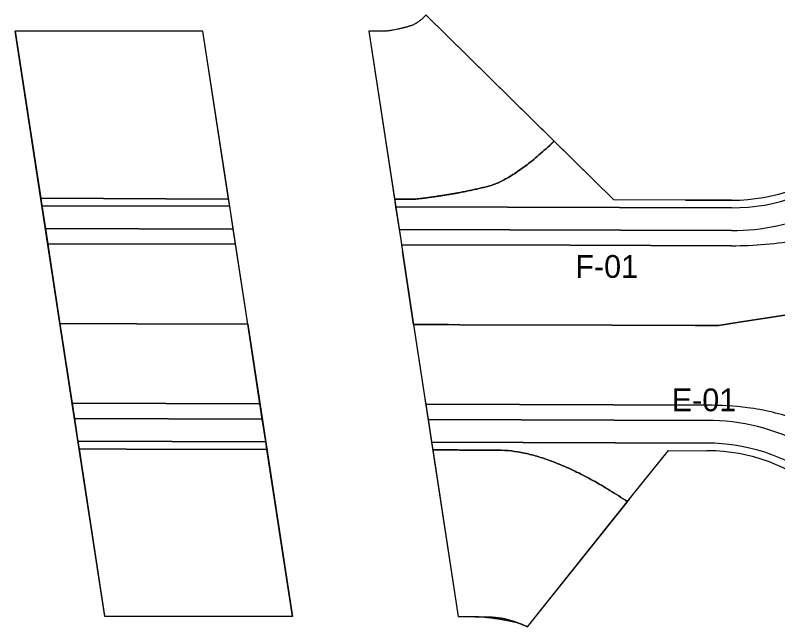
# Model space of a CAD drawing. Extents: x 5196716 to 5200291, y 3709146 to 3713154.
# Drawn here: x 5197139.9 to 5197340.6, y 3709270.7 to 3709431.8 of the extents above; entities that cross this region are included whole.
import ezdxf

# ---------------------------------------------------------------- set-up
doc = ezdxf.new("R2010")
doc.units = 0
for name, color, linetype in [('Drainage-Area', 7, 'Continuous'), ('dsnTextNote', 7, 'Continuous'), ('Level 1', 7, 'Continuous'), ('Level 2', 7, 'Continuous'), ('Level 3', 7, 'Continuous'), ('Level 4', 7, 'Continuous')]:
    doc.layers.add(name, color=color, linetype=linetype)

msp = doc.modelspace()

# ---------------------------------------------------------------- linework, layer by layer
at = {"layer": 'Drainage-Area'}
for p, q in [((5197151.63, 3709350.57), (5197139.87, 3709427.59)), ((5197189.27, 3709427.57), (5197139.87, 3709427.59)), ((5197139.87, 3709427.59), (5197148.88, 3709368.54)), ((5197201.05, 3709350.42), (5197195.7, 3709385.44)), ((5197195.7, 3709385.44), (5197195.7, 3709385.44)), ((5197195.7, 3709385.44), (5197195.7, 3709385.44)), ((5197316.34, 3709383.09), (5197328.45, 3709383.06)), ((5197148.88, 3709368.54), (5197151.63, 3709350.57)), ((5197151.63, 3709350.57), (5197201.05, 3709350.42))]:
    msp.add_line(p, q, dxfattribs=at)
for points in [[(5197195.7, 3709385.44), (5197189.27, 3709427.57)], [(5197251.88, 3709350.28), (5197244.74, 3709350.3), (5197241.79, 3709369.59)], [(5197318.88, 3709350.08), (5197325, 3709350.07), (5197330.45, 3709350.92)]]:
    msp.add_lwpolyline(points, dxfattribs=at)
msp.add_lwpolyline([(5197151.63, 3709350.57), (5197201.05, 3709350.42), (5197212.81, 3709273.4), (5197163.41, 3709273.42)], close=True, dxfattribs=at)
at = {"layer": 'Level 1'}
for p, q in [((5197297.45, 3709383.15), (5197248, 3709431.77)), ((5197235.97, 3709427.56), (5197232.94, 3709427.56)), ((5197232.94, 3709427.56), (5197241.42, 3709372.05)), ((5197322.58, 3709383.07), (5197297.45, 3709383.15)), ((5197328.45, 3709383.06), (5197322.58, 3709383.07)), ((5197241.42, 3709372.05), (5197241.53, 3709371.31)), ((5197241.53, 3709371.31), (5197241.79, 3709369.59)), ((5197346.68, 3709353.45), (5197325, 3709350.07)), ((5197330.45, 3709350.92), (5197346.68, 3709353.45)), ((5197256.88, 3709350.26), (5197244.74, 3709350.3)), ((5197244.74, 3709350.3), (5197247.46, 3709332.48)), ((5197251.88, 3709350.28), (5197253.88, 3709350.27)), ((5197296.88, 3709350.15), (5197256.88, 3709350.26)), ((5197324.26, 3709350.07), (5197296.88, 3709350.15)), ((5197325, 3709350.07), (5197324.26, 3709350.07)), ((5197247.46, 3709332.48), (5197247.95, 3709329.29)), ((5197247.95, 3709329.29), (5197248.55, 3709325.3)), ((5197302.39, 3709305.33), (5197311.79, 3709317.1)), ((5197311.79, 3709317.1), (5197321.94, 3709317.07)), ((5197274.72, 3709270.7), (5197302.39, 3709305.33)), ((5197256.48, 3709273.38), (5197259.52, 3709273.38))]:
    msp.add_line(p, q, dxfattribs=at)
for points in [[(5197241.79, 3709369.59), (5197244.74, 3709350.3), (5197251.88, 3709350.28)], [(5197324.26, 3709350.07), (5197325, 3709350.07), (5197330.45, 3709350.92)], [(5197253.88, 3709350.27), (5197256.88, 3709350.26), (5197296.88, 3709350.15)], [(5197296.88, 3709350.15), (5197318.88, 3709350.08), (5197324.26, 3709350.07)], [(5197248.55, 3709325.3), (5197254.02, 3709289.52), (5197256.48, 3709273.38)], [(5197259.52, 3709273.38), (5197259.59, 3709273.38)]]:
    msp.add_lwpolyline(points, dxfattribs=at)
for centre, start, end in [((5197328.59, 3709431.06), 269.8345, 309.8603), ((5197321.8, 3709269.07), 89.4347, 89.8345), ((5197321.8, 3709269.07), 50.7893, 89.4347)]:
    msp.add_arc(centre, 48, start, end, dxfattribs=at)
for points in [[(5197247.8, 3709431.58), (5197245.73, 3709429.59), (5197242.85, 3709428.58), (5197240.45, 3709428.08)], [(5197248, 3709431.77), (5197247.93, 3709431.7), (5197247.87, 3709431.64), (5197247.8, 3709431.58)], [(5197240.45, 3709428.08), (5197237.95, 3709427.55), (5197235.97, 3709427.56), (5197235.97, 3709427.56)], [(5197259.59, 3709273.38), (5197260.46, 3709273.37), (5197269.42, 3709273.2), (5197274.72, 3709270.7)]]:
    msp.add_open_spline(points, degree=2, dxfattribs=at)
at = {"layer": 'Level 2'}
for p, q in [((5197196.31, 3709381.44), (5197146.89, 3709381.58)), ((5197146.89, 3709381.58), (5197147.81, 3709375.58)), ((5197197.23, 3709375.43), (5197196.31, 3709381.44)), ((5197328.45, 3709381.06), (5197240, 3709381.31)), ((5197240, 3709381.31), (5197240.92, 3709375.31)), ((5197147.81, 3709375.58), (5197197.23, 3709375.43)), ((5197240.92, 3709375.31), (5197328.43, 3709375.06)), ((5197148.42, 3709371.58), (5197148.88, 3709368.54)), ((5197197.84, 3709371.43), (5197148.42, 3709371.58)), ((5197201.05, 3709350.42), (5197197.84, 3709371.43)), ((5197241.53, 3709371.31), (5197241.79, 3709369.59)), ((5197148.88, 3709368.54), (5197151.63, 3709350.57)), ((5197330.45, 3709350.92), (5197346.68, 3709353.45)), ((5197346.68, 3709353.45), (5197330.45, 3709350.92)), ((5197325, 3709350.07), (5197330.45, 3709350.92)), ((5197330.45, 3709350.92), (5197325, 3709350.07)), ((5197151.63, 3709350.57), (5197171.88, 3709350.51)), ((5197171.88, 3709350.51), (5197201.05, 3709350.42)), ((5197201.05, 3709350.42), (5197171.88, 3709350.51)), ((5197204.26, 3709329.41), (5197201.05, 3709350.42)), ((5197251.88, 3709350.28), (5197244.74, 3709350.3)), ((5197244.74, 3709350.3), (5197247.46, 3709332.48)), ((5197251.88, 3709350.28), (5197253.88, 3709350.27)), ((5197253.88, 3709350.27), (5197251.88, 3709350.28)), ((5197253.88, 3709350.27), (5197256.88, 3709350.26)), ((5197256.88, 3709350.26), (5197296.88, 3709350.15)), ((5197318.88, 3709350.08), (5197296.88, 3709350.15)), ((5197324.26, 3709350.07), (5197325, 3709350.07)), ((5197247.46, 3709332.48), (5197247.95, 3709329.29)), ((5197154.84, 3709329.56), (5197154.84, 3709329.56)), ((5197154.84, 3709329.56), (5197204.26, 3709329.41)), ((5197247.95, 3709329.29), (5197321.98, 3709329.07)), ((5197155.45, 3709325.56), (5197156.36, 3709319.55)), ((5197204.87, 3709325.41), (5197155.45, 3709325.56)), ((5197205.79, 3709319.41), (5197204.87, 3709325.41)), ((5197321.97, 3709325.07), (5197248.55, 3709325.3)), ((5197248.55, 3709325.3), (5197249.47, 3709319.28)), ((5197156.36, 3709319.55), (5197205.79, 3709319.41)), ((5197249.47, 3709319.28), (5197321.95, 3709319.07))]:
    msp.add_line(p, q, dxfattribs=at)
for points in [[(5197328.42, 3709371.06), (5197285.89, 3709371.18), (5197241.53, 3709371.31)], [(5197241.79, 3709369.59), (5197244.74, 3709350.3), (5197251.88, 3709350.28)], [(5197171.88, 3709350.51), (5197151.63, 3709350.57), (5197154.84, 3709329.56)], [(5197296.88, 3709350.15), (5197256.88, 3709350.26), (5197253.88, 3709350.27)], [(5197296.88, 3709350.15), (5197318.88, 3709350.08), (5197324.26, 3709350.07)], [(5197325, 3709350.07), (5197324.26, 3709350.07), (5197318.88, 3709350.08)]]:
    msp.add_lwpolyline(points, dxfattribs=at)
for centre, radius, start, end in [((5197328.59, 3709431.06), 50, 269.8345, 309.4106), ((5197328.59, 3709431.06), 56, 269.8345, 294.4582), ((5197328.7, 3709468.56), 97.5, 269.8354, 280.3656), ((5197321.72, 3709241.57), 87.5, 82.8549, 89.8345), ((5197325.15, 3709268.86), 60, 70.1272, 82.8549), ((5197321.8, 3709269.07), 56, 62.2868, 89.8345), ((5197321.8, 3709269.07), 50, 54.334, 89.8345)]:
    msp.add_arc(centre, radius, start, end, dxfattribs=at)
at = {"layer": 'Level 3'}
for p, q in [((5197281.71, 3709398.62), (5197248, 3709431.77)), ((5197139.87, 3709427.59), (5197146.59, 3709383.58)), ((5197189.27, 3709427.57), (5197139.87, 3709427.59)), ((5197196.02, 3709383.36), (5197189.27, 3709427.57)), ((5197235.97, 3709427.56), (5197232.94, 3709427.56)), ((5197232.94, 3709427.56), (5197239.7, 3709383.31)), ((5197146.59, 3709383.58), (5197196.02, 3709383.36)), ((5197239.7, 3709383.31), (5197242.73, 3709383.3)), ((5197169.15, 3709317.52), (5197156.67, 3709317.55)), ((5197156.67, 3709317.55), (5197163.39, 3709273.54)), ((5197206.09, 3709317.41), (5197169.15, 3709317.52)), ((5197212.81, 3709273.4), (5197206.09, 3709317.41)), ((5197252.81, 3709317.27), (5197249.78, 3709317.28)), ((5197249.78, 3709317.28), (5197254.02, 3709289.52)), ((5197274.72, 3709270.7), (5197301.05, 3709303.65)), ((5197254.02, 3709289.52), (5197256.48, 3709273.4)), ((5197163.39, 3709273.54), (5197212.81, 3709273.4)), ((5197256.48, 3709273.4), (5197256.48, 3709273.38)), ((5197256.48, 3709273.38), (5197259.52, 3709273.38))]:
    msp.add_line(p, q, dxfattribs=at)
for points in [[(5197247.8, 3709431.58), (5197245.73, 3709429.59), (5197242.85, 3709428.58), (5197240.45, 3709428.08)], [(5197248, 3709431.77), (5197247.93, 3709431.7), (5197247.87, 3709431.64), (5197247.8, 3709431.58)], [(5197240.45, 3709428.08), (5197237.95, 3709427.55), (5197235.97, 3709427.56), (5197235.97, 3709427.56)], [(5197249.78, 3709383.91), (5197257.64, 3709385.03), (5197270.57, 3709388.26), (5197280.55, 3709397.5)], [(5197280.55, 3709397.5), (5197280.94, 3709397.87), (5197281.33, 3709398.24), (5197281.71, 3709398.62)], [(5197242.73, 3709383.3), (5197242.73, 3709383.3), (5197245.51, 3709383.3), (5197249.78, 3709383.91)], [(5197301.05, 3709303.65), (5197280.77, 3709317.19), (5197252.81, 3709317.27), (5197252.81, 3709317.27)], [(5197259.52, 3709273.38), (5197259.52, 3709273.38), (5197259.52, 3709273.38), (5197259.52, 3709273.38)], [(5197259.52, 3709273.38), (5197259.62, 3709273.38), (5197263.64, 3709273.35), (5197267.96, 3709272.62)], [(5197267.96, 3709272.62), (5197270.32, 3709272.23), (5197272.77, 3709271.62), (5197274.72, 3709270.7)]]:
    msp.add_open_spline(points, degree=2, dxfattribs=at)
at = {"layer": 'Level 4'}
for p, q in [((5197297.45, 3709383.15), (5197281.71, 3709398.62)), ((5197196.02, 3709383.36), (5197146.59, 3709383.58)), ((5197146.59, 3709383.58), (5197146.89, 3709381.58)), ((5197196.31, 3709381.44), (5197196.02, 3709383.36)), ((5197242.73, 3709383.3), (5197239.7, 3709383.31)), ((5197239.7, 3709383.31), (5197240, 3709381.31)), ((5197328.45, 3709383.06), (5197322.58, 3709383.07)), ((5197146.89, 3709381.58), (5197196.31, 3709381.44)), ((5197240, 3709381.31), (5197328.45, 3709381.06)), ((5197147.81, 3709375.58), (5197148.42, 3709371.58)), ((5197197.23, 3709375.43), (5197147.81, 3709375.58)), ((5197197.84, 3709371.43), (5197197.23, 3709375.43)), ((5197328.43, 3709375.06), (5197240.92, 3709375.31)), ((5197240.92, 3709375.31), (5197241.42, 3709372.05)), ((5197148.42, 3709371.58), (5197197.84, 3709371.43)), ((5197241.42, 3709372.05), (5197241.53, 3709371.31)), ((5197244.74, 3709350.3), (5197256.48, 3709273.38)), ((5197154.84, 3709329.56), (5197155.45, 3709325.56)), ((5197204.26, 3709329.41), (5197154.84, 3709329.56)), ((5197204.87, 3709325.41), (5197204.26, 3709329.41)), ((5197321.98, 3709329.07), (5197247.95, 3709329.29)), ((5197247.95, 3709329.29), (5197248.55, 3709325.3)), ((5197155.45, 3709325.56), (5197204.87, 3709325.41)), ((5197248.55, 3709325.3), (5197248.56, 3709325.29)), ((5197248.56, 3709325.29), (5197321.97, 3709325.07)), ((5197156.36, 3709319.55), (5197156.67, 3709317.55)), ((5197205.79, 3709319.41), (5197156.36, 3709319.55)), ((5197206.09, 3709317.41), (5197205.79, 3709319.41)), ((5197321.95, 3709319.07), (5197249.47, 3709319.28)), ((5197249.47, 3709319.28), (5197249.78, 3709317.28)), ((5197156.67, 3709317.55), (5197169.15, 3709317.52)), ((5197169.15, 3709317.52), (5197206.09, 3709317.41)), ((5197249.78, 3709317.28), (5197252.81, 3709317.27)), ((5197302.39, 3709305.33), (5197311.79, 3709317.1)), ((5197311.79, 3709317.1), (5197321.94, 3709317.07)), ((5197301.05, 3709303.65), (5197302.39, 3709305.33))]:
    msp.add_line(p, q, dxfattribs=at)
for points in [[(5197322.58, 3709383.07), (5197316.34, 3709383.09), (5197297.45, 3709383.15)], [(5197241.53, 3709371.31), (5197285.89, 3709371.18), (5197328.42, 3709371.06)]]:
    msp.add_lwpolyline(points, dxfattribs=at)
for centre, radius, start, end in [((5197328.59, 3709431.06), 48, 269.8345, 309.8603), ((5197328.59, 3709431.06), 50, 269.8345, 309.4106), ((5197328.59, 3709431.06), 56, 269.8345, 294.4582), ((5197328.7, 3709468.56), 97.5, 269.8354, 280.3656), ((5197321.72, 3709241.57), 87.5, 82.8549, 89.8345), ((5197325.15, 3709268.86), 60, 70.1272, 82.8549), ((5197321.8, 3709269.07), 56, 62.2868, 89.8345), ((5197321.8, 3709269.07), 50, 54.334, 89.8345), ((5197321.8, 3709269.07), 48, 89.4347, 89.8345), ((5197321.8, 3709269.07), 48, 50.7893, 89.4347)]:
    msp.add_arc(centre, radius, start, end, dxfattribs=at)
for points in [[(5197280.55, 3709397.5), (5197270.57, 3709388.26), (5197257.64, 3709385.03), (5197249.78, 3709383.91)], [(5197281.71, 3709398.62), (5197281.33, 3709398.24), (5197280.94, 3709397.87), (5197280.55, 3709397.5)], [(5197249.78, 3709383.91), (5197245.51, 3709383.3), (5197242.73, 3709383.3), (5197242.73, 3709383.3)], [(5197252.81, 3709317.27), (5197252.81, 3709317.27), (5197280.77, 3709317.19), (5197301.05, 3709303.65)]]:
    msp.add_open_spline(points, degree=2, dxfattribs=at)

# ---------------------------------------------------------------- texts
at = {"layer": 'dsnTextNote'}
for s, p in [('F-01', (5197287.31, 3709362.6)), ('E-01', (5197312.69, 3709327.46))]:
    msp.add_text(s, height=6, dxfattribs=at).set_placement(p)

doc.saveas('drawing.dxf')
